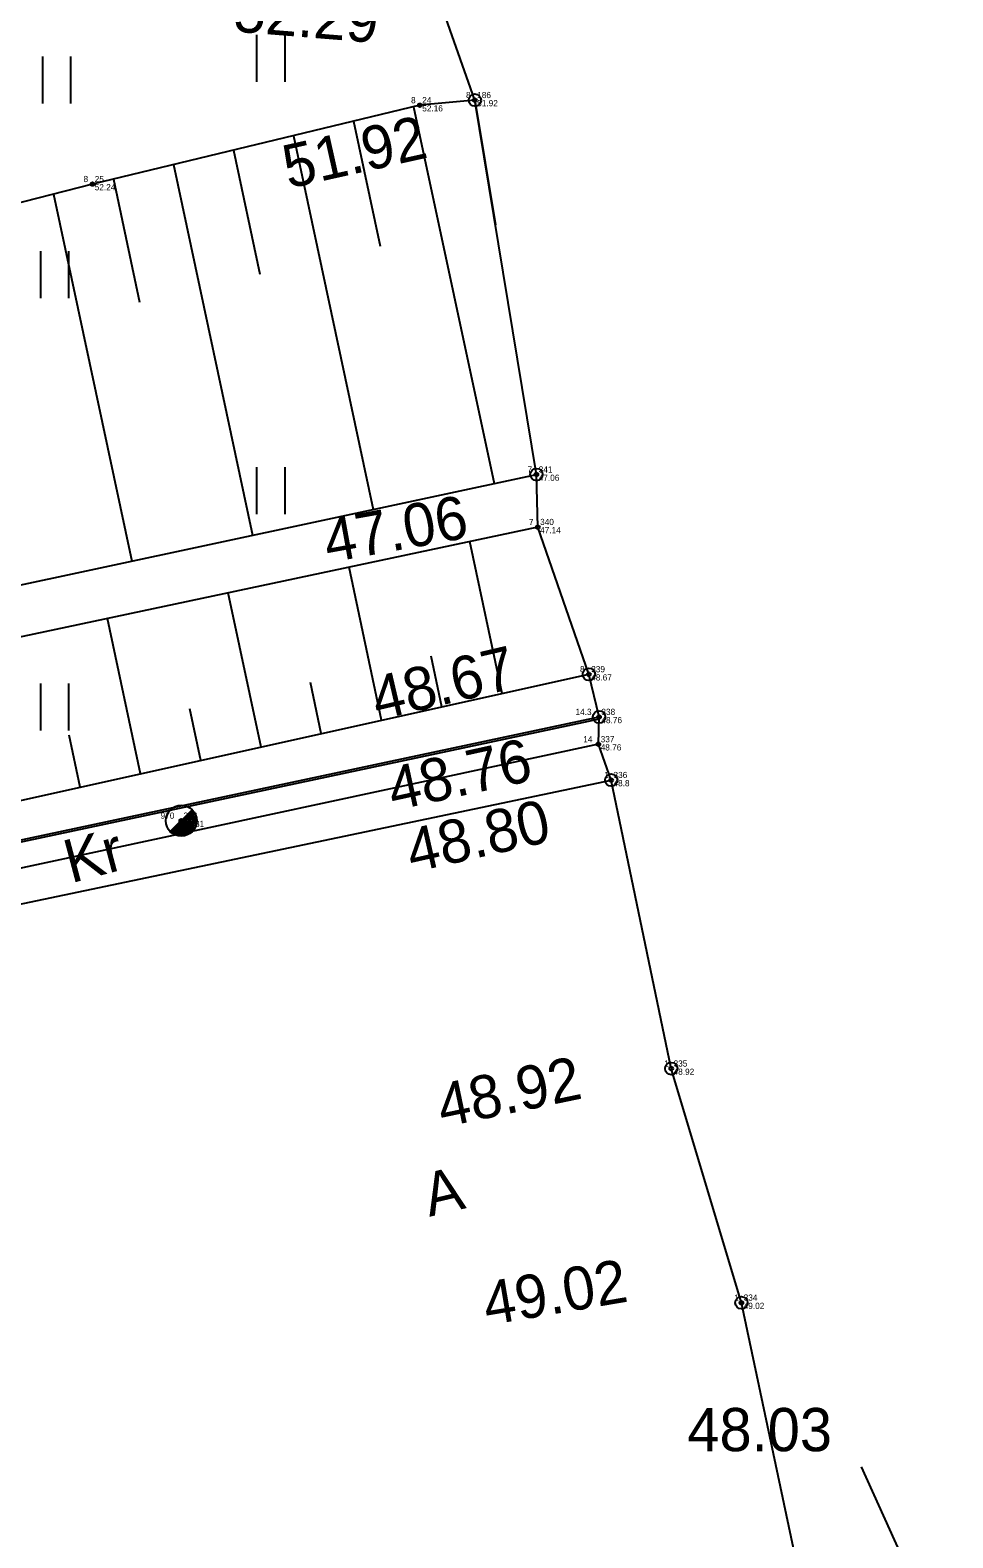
# Model space of a CAD drawing. Extents: x 543497 to 552146, y 6567125 to 6579845.
# Drawn here: x 546517.61 to 546532.55, y 6577795.55 to 6577819.96 of the extents above; entities that cross this region are included whole.
import ezdxf

# ---------------------------------------------------------------- set-up
doc = ezdxf.new("R2010")
doc.units = 0
for name, color, linetype in [('xref_Kangru tee 1_geodeesia$0$ABIJOONIS', 7, 'Continuous'), ('xref_Kangru tee 1_geodeesia$0$HALJASTUS', 7, 'Continuous'), ('xref_Kangru tee 1_geodeesia$0$korgus-EH2000', 7, 'Continuous'), ('xref_Kangru tee 1_geodeesia$0$Liiklus', 7, 'Continuous'), ('xref_Kangru tee 1_geodeesia$0$mootkood', 7, 'Continuous'), ('xref_Kangru tee 1_geodeesia$0$MOOTKORG-eh2000', 7, 'Continuous'), ('xref_Kangru tee 1_geodeesia$0$mootmpunkt', 7, 'Continuous'), ('xref_Kangru tee 1_geodeesia$0$MOOTNR', 7, 'Continuous'), ('xref_Kangru tee 1_geodeesia$0$MOOTPIIR', 7, 'Continuous'), ('xref_Kangru tee 1_geodeesia$0$Post', 7, 'Continuous'), ('xref_Kangru tee 1_geodeesia$0$RELJEEF', 7, 'Continuous'), ('xref_Kangru tee 1_geodeesia$0$TEE', 7, 'Continuous')]:
    doc.layers.add(name, color=color, linetype=linetype)

# ---------------------------------------------------------------- blocks, each defined once
blk = doc.blocks.new('xref_Kangru tee 1_geodeesia$0$plpost')
blk.add_line((-0.354, -0.353), (0.353, 0.354))
blk.add_circle((0, 0), 0.5)
for radius, start, end in [(0.45, 224.8541, 45.0356), (0.4, 224.8427, 45.047), (0.35, 224.8281, 45.0616), (0.3, 224.8087, 45.081), (0.25, 224.7814, 45.1083), (0.2, 224.7406, 45.1491), (0.15, 224.6725, 45.2172), (0.1, 224.5363, 45.3534), (0.05, 224.1278, 45.7619)]:
    blk.add_arc((0, 0), radius, start, end)
blk = doc.blocks.new('xref_Kangru tee 1_geodeesia$0$hein')
for p, q in [((-0.455, 0.761), (-0.455, -0.761)), ((0.455, 0.761), (0.455, -0.761))]:
    blk.add_line(p, q)

msp = doc.modelspace()

# ---------------------------------------------------------------- linework, layer by layer
at = {"layer": 'xref_Kangru tee 1_geodeesia$0$ABIJOONIS'}
msp.add_lwpolyline([(546532.546, 6577793.426), (546531.066, 6577796.696)], dxfattribs=at)
at = {"layer": 'xref_Kangru tee 1_geodeesia$0$korgus-EH2000'}
for centre in [(546524.807, 6577818.824), (546525.803, 6577812.761), (546526.653, 6577809.528), (546526.818, 6577808.837), (546527.014, 6577807.815), (546527.987, 6577803.144), (546529.122, 6577799.354)]:
    msp.add_circle(centre, 0.1, dxfattribs=at)
at = {"layer": 'xref_Kangru tee 1_geodeesia$0$Liiklus'}
for points in [[(546354.422, 6577770.53), (546379.059, 6577776.787), (546402.027, 6577782.256), (546425.602, 6577787.345), (546450.508, 6577792.703), (546473.299, 6577797.469), (546500.398, 6577803.187), (546526.826, 6577808.807)], [(546526.806, 6577808.395), (546500.782, 6577802.819), (546473.425, 6577797.082), (546450.905, 6577792.308), (546425.741, 6577786.914), (546402.021, 6577781.761), (546379.276, 6577776.325), (546354.305, 6577769.937)]]:
    msp.add_lwpolyline(points, dxfattribs=at)
at = {"layer": 'xref_Kangru tee 1_geodeesia$0$mootmpunkt'}
for centre in [(546523.917, 6577818.741), (546524.807, 6577818.824), (546518.614, 6577817.464), (546525.803, 6577812.761), (546525.826, 6577811.912), (546526.653, 6577809.528), (546526.818, 6577808.837), (546526.806, 6577808.395), (546527.014, 6577807.815), (546520.052, 6577807.157), (546527.987, 6577803.144), (546529.122, 6577799.354)]:
    msp.add_circle(centre, 0.03, dxfattribs=at)
at = {"layer": 'xref_Kangru tee 1_geodeesia$0$MOOTPIIR'}
msp.add_lwpolyline([(546530.102, 6577794.743), (546529.122, 6577799.354), (546527.987, 6577803.144), (546527.014, 6577807.815), (546526.806, 6577808.395), (546526.818, 6577808.837), (546526.653, 6577809.528), (546525.826, 6577811.912), (546525.803, 6577812.761), (546524.807, 6577818.824), (546524.335, 6577820.155)], dxfattribs=at)
at = {"layer": 'xref_Kangru tee 1_geodeesia$0$RELJEEF'}
for p, q in [((546524.807, 6577818.824), (546525.139, 6577816.803)), ((546523.814, 6577818.716), (546525.117, 6577812.615)), ((546521.869, 6577818.248), (546523.162, 6577812.197)), ((546522.842, 6577818.482), (546523.274, 6577816.457)), ((546520.897, 6577818.014), (546521.326, 6577816.005)), ((546519.925, 6577817.78), (546521.207, 6577811.779)), ((546518.953, 6577817.546), (546519.378, 6577815.554)), ((546517.983, 6577817.303), (546519.252, 6577811.361)), ((546525.249, 6577809.217), (546524.726, 6577811.678)), ((546523.296, 6577808.784), (546522.77, 6577811.263)), ((546521.344, 6577808.351), (546520.814, 6577810.848)), ((546519.391, 6577807.919), (546518.857, 6577810.432)), ((546524.273, 6577809), (546524.098, 6577809.824)), ((546522.32, 6577808.568), (546522.144, 6577809.397)), ((546520.367, 6577808.135), (546520.19, 6577808.97)), ((546518.415, 6577807.702), (546518.236, 6577808.543))]:
    msp.add_line(p, q, dxfattribs=at)
for points in [[(546524.807, 6577818.824), (546523.917, 6577818.741), (546518.614, 6577817.464), (546508.34, 6577814.841), (546490.791, 6577811.344), (546486.302, 6577810.35), (546469.874, 6577807.015), (546463.26, 6577805.773), (546455.756, 6577804.12), (546437.742, 6577800.627), (546421.669, 6577797.236), (546404.043, 6577793.342), (546385.032, 6577788.476), (546373.604, 6577785.585), (546371.653, 6577784.58), (546361.605, 6577782.026), (546351.751, 6577779.191)], [(546354.056, 6577774.459), (546378.502, 6577780.322), (546401.434, 6577786.359), (546425.431, 6577791.18), (546449.636, 6577796.396), (546472.918, 6577801.529), (546499.707, 6577807.186), (546525.803, 6577812.761)], [(546525.826, 6577811.912), (546499.884, 6577806.403), (546472.988, 6577800.991), (546449.823, 6577796.032), (546425.576, 6577790.519), (546401.581, 6577785.595), (546378.638, 6577779.848), (546354.289, 6577773.806)], [(546354.547, 6577770.799), (546378.469, 6577777.139), (546401.955, 6577782.667), (546425.454, 6577787.953), (546450.273, 6577793.376), (546473.755, 6577798.336), (546500.355, 6577803.7), (546526.653, 6577809.528)]]:
    msp.add_lwpolyline(points, dxfattribs=at)
at = {"layer": 'xref_Kangru tee 1_geodeesia$0$TEE'}
for points in [[(546354.431, 6577770.502), (546379.126, 6577776.583), (546402.076, 6577782.095), (546425.594, 6577787.381), (546450.507, 6577792.739), (546473.294, 6577797.509), (546500.394, 6577803.225), (546526.818, 6577808.837)], [(546354.298, 6577769.359), (546379.481, 6577775.849), (546402.133, 6577781.358), (546425.535, 6577786.353), (546450.991, 6577791.759), (546473.442, 6577796.551), (546501.171, 6577802.392), (546527.014, 6577807.815)]]:
    msp.add_lwpolyline(points, dxfattribs=at)

# ---------------------------------------------------------------- block references
at = {"layer": 'xref_Kangru tee 1_geodeesia$0$HALJASTUS', "xscale": 0.5, "yscale": 0.5}
for p in [(546521.5, 6577819.5), (546518.032, 6577819.148), (546518, 6577816), (546521.5, 6577812.5), (546518, 6577809)]:
    msp.add_blockref('xref_Kangru tee 1_geodeesia$0$hein', p, dxfattribs=at)
at = {"layer": 'xref_Kangru tee 1_geodeesia$0$Post', "xscale": 0.5, "yscale": 0.5}
msp.add_blockref('xref_Kangru tee 1_geodeesia$0$plpost', (546520.052, 6577807.157), dxfattribs=at)

# ---------------------------------------------------------------- texts
at = {"layer": 'xref_Kangru tee 1_geodeesia$0$ABIJOONIS'}
msp.add_text('48.03', height=0.7, dxfattribs=at).set_placement((546528.247, 6577796.95))
at = {"layer": 'xref_Kangru tee 1_geodeesia$0$korgus-EH2000'}
for s, rotation, p in [(' 52.29 ', 355.4124, (546520.624, 6577819.957)), (' 51.92 ', 12.591, (546521.533, 6577817.333)), (' 47.06 ', 10.2536, (546522.173, 6577811.284)), (' 48.67 ', 13.188, (546522.978, 6577808.723)), (' 48.76 ', 12.3548, (546523.231, 6577807.26)), (' 48.80 ', 12.7712, (546523.535, 6577806.257)), (' 48.92 ', 11.7706, (546524.026, 6577802.136)), (' 49.02 ', 9.6226, (546524.748, 6577798.942))]:
    msp.add_text(s, height=0.7, rotation=rotation, dxfattribs=at).set_placement(p)
at = {"layer": 'xref_Kangru tee 1_geodeesia$0$mootkood'}
for s, p in [(' 8', (546523.736, 6577818.774)), (' 8', (546524.626, 6577818.857)), (' 8', (546518.433, 6577817.497)), (' 7', (546525.622, 6577812.794)), (' 7', (546525.645, 6577811.945)), (' 8', (546526.472, 6577809.561)), (' 14.3', (546526.399, 6577808.87)), (' 14', (546526.525, 6577808.428)), (' 1', (546526.862, 6577807.848)), (' 970', (546519.681, 6577807.19)), (' 1', (546527.835, 6577803.177)), (' 1', (546528.97, 6577799.387))]:
    msp.add_text(s, height=0.1, dxfattribs=at).set_placement(p)
at = {"layer": 'xref_Kangru tee 1_geodeesia$0$MOOTKORG-eh2000'}
for s, p in [(' 52.16', (546523.917, 6577818.641)), (' 51.92', (546524.807, 6577818.724)), (' 52.24', (546518.614, 6577817.364)), (' 47.06', (546525.803, 6577812.661)), (' 47.14', (546525.826, 6577811.812)), (' 48.67', (546526.653, 6577809.428)), (' 48.76', (546526.818, 6577808.737)), (' 48.76', (546526.806, 6577808.295)), (' 48.8', (546527.014, 6577807.715)), (' 48.81', (546520.052, 6577807.057)), (' 48.92', (546527.987, 6577803.044)), (' 49.02', (546529.122, 6577799.254))]:
    msp.add_text(s, height=0.1, dxfattribs=at).set_placement(p)
at = {"layer": 'xref_Kangru tee 1_geodeesia$0$MOOTNR'}
for s, p in [(' 24', (546523.917, 6577818.774)), (' 186', (546524.807, 6577818.857)), (' 25', (546518.614, 6577817.497)), (' 341', (546525.803, 6577812.794)), (' 340', (546525.826, 6577811.945)), (' 339', (546526.653, 6577809.561)), (' 338', (546526.818, 6577808.87)), (' 337', (546526.806, 6577808.428)), (' 336', (546527.014, 6577807.848)), (' 342', (546520.052, 6577807.19)), (' 335', (546527.987, 6577803.177)), (' 334', (546529.122, 6577799.387))]:
    msp.add_text(s, height=0.1, dxfattribs=at).set_placement(p)
at = {"layer": 'xref_Kangru tee 1_geodeesia$0$TEE'}
for s, rotation, p in [('Kr', 14.8982, (546518.267, 6577806.143)), ('A', 13.2438, (546524.07, 6577800.744))]:
    msp.add_text(s, height=0.7, rotation=rotation, dxfattribs=at).set_placement(p)

doc.saveas('drawing.dxf')
